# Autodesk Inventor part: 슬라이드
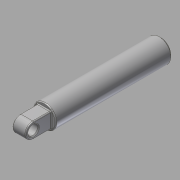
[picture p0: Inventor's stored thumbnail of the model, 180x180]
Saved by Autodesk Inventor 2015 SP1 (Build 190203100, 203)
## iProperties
Created: 2016-02
Part Number: 슬라이드
Material: 강철, 연강
Document SubType Name: Modeling
Designer: test
Density: 1 g/cm^3
Appearance: 강철
Author: test
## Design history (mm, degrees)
sketch "스케치2"
  geometry: C1 r 6 at (0, 0); 1 further point
  constraints: 1 centre point, 1 coincident
  dimensions: "d0" = 12 diameter of C1
extrude "돌출1" new body sketch "스케치2" distance "d1" = 60; taper "d2" = 0 deg
hole "구멍1" diameter "d5" = 5.917; stored, may be unused: countersink angle "d9" = 90 deg, drill point angle "d11" = 118 deg; dims "d3" = 10, "d4" = 10, "d6" = 10, "d7" = 4, "d8" = 2, "d10" = 12
chamfer "모따기1" distance "d12" = 1; stored, may be unused: second distance "d13" = 2, angle "d14" = 45 deg
sketch "스케치3"
  geometry: L1 (0, 6)-(0, -6) reference; L2 (0, 4)-(-9, 4); L3 (-9, -4)-(0, -4); L4 (0, -4)-(0, 4); C1 r 2.5 at (-9, 0); A1 r 4 centre (-9, 0) between (-9, 4) and (-9, -4); 2 further points
  constraints: 6 end point, 2 centre point, 2 point on circle, 2 tangent, 1 coincident, 1 horizontal, 1 horizontal alignment, 1 midpoint, 1 parallel, 1 point on line, 1 vertical
  dimensions: "d15" = 13 dimension on A1 L1; "d16" = 8 distance between parallel lines of L3 L2; "d17" = 5 diameter of C1
extrude "돌출2" join sketch "스케치3" stored distance "d18" = 7; taper "d19" = 0 deg
chamfer "모따기2" distance "d20" = 0.5; stored, may be unused: second distance "d21" = 2, angle "d22" = 45 deg
fillet "모깎기1" dims "d23" = 0.5
fillet "모깎기2" dims "d24" = 0.5
fillet "모깎기3" dims "d25" = 0.5
node "솔리드1"
